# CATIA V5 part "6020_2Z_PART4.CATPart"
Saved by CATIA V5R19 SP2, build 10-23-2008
Part number: 6020_2Z_PART4
Bounding box of the stored display mesh (mm): x 22.238 to 22.943, y -68.91 to 68.91, z -68.981 to 68.981
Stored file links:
  G:\EU_thinkMotion\CFAO_2010\MMS_groupe2\MMS_groupe2\OK\nrosalie\nrosalie_cfao_support_d_arme_legere_final\6020_2Z_PART4.CATPart
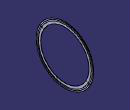
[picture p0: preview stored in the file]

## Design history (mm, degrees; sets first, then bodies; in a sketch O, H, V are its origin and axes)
Set1
  Point1: (0, 0, 0)
  Point2: (1, 0, 0)
  Point3: (0, 1, 0)
  Plane1: type 3Points, Element1 Point1, Element2 Point2, Element3 Point3
Body1 (main body)
  Sketch1 on Plane1, origin (0, 0, 0), H (1, 0, 0), V (0, 1, 0)
    point P1 (22.238, 66.2161)
    point P2 (22.238, 63.5)
    line L1 (22.238, 66.2161) -> (22.238, 63.5)
    point P3 (22.238, 63.5)
    point P4 (22.5905, 58)
    line L2 (22.238, 63.5) -> (22.5905, 58)
    point P5 (22.5905, 58)
    point P6 (22.943, 58)
    line L3 (22.5905, 58) -> (22.943, 58)
    point P7 (22.943, 58)
    point P8 (22.943, 63.5)
    line L4 (22.943, 58) -> (22.943, 63.5)
    point P9 (22.943, 63.5)
    point P10 (22.7667, 66.25)
    line L5 (22.943, 63.5) -> (22.7668, 66.25)
    point P11 (22.7667, 66.25)
    point P12 (22.943, 69)
    line L6 (22.7667, 66.25) -> (22.943, 69)
    point P13 (22.943, 69)
    point P14 (22.5905, 69)
    line L7 (22.943, 69) -> (22.5905, 69)
    point P15 (22.5905, 69)
    point P16 (22.238, 66.2161)
    line L8 (22.5905, 69) -> (22.238, 66.2161)
    point P17 (50, 0)
    point P18 (-50, 0)
    axis line L9 (50, 0) -> (-50, 0)
    point P19 (22.238, 66.2161)
    point P20 (22.238, 63.5)
    point P21 (22.238, 63.5)
    point P22 (22.5905, 58)
    point P23 (22.5905, 58)
    point P24 (22.943, 58)
    point P25 (22.943, 58)
    point P26 (22.943, 63.5)
    point P27 (22.943, 63.5)
    point P28 (22.7668, 66.25)
    point P29 (22.7667, 66.25)
    point P30 (22.943, 69)
    point P31 (22.943, 69)
    point P32 (22.5905, 69)
    point P33 (22.5905, 69)
    point P34 (22.238, 66.2161)
    coincidence: P19 P34, P20 P21, P22 P23, P24 P25, P26 P27, P28 P29, P30 P31, P32 P33
  Shaft1: profile Sketch1, axis Sketch1.L9, angle 360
